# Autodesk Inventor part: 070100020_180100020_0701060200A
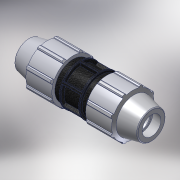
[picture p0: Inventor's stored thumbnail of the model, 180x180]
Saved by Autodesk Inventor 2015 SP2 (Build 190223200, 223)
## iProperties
Created: 2017-02
Part Number: 070100020_180100020_0701060200A
Material: PVC-Piping
Description: PLASSON COUPLER 20-20
Document SubType Name: Modeling
Designer: KIM
Mass: 92.6774 g
Surface Area: 199.44 cm^2
Volume: 66.1981 cm^3
Density: 1.4 g/cm^3
Appearance: PTFE
Author: KIM
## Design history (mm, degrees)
derived "07010.ipt"
feature "Solid1::07010.ipt"
tag "TaggingFeature1"
body "Solid1"
other parameters: "d1" = 122, "d4" = 10.16667, "d5" = 17.42857, "d7" = 48, "d8" = 36, "d9" = 17.42857, "d11" = 1.74286, "d12" = 38.4, "d13" = 120 deg, "d15" = 12 deg, "d16" = 43.2, "d18" = 1, "d19" = 35 deg, "d20" = 17.5 deg, "d21" = 44.64, "d23" = 0, "d25" = 360 deg, "d27" = 0.96, "d33" = 0.4, "d34" = 2.4, "d36" = 0, "d37" = 0.4, "d38" = 0.4, "d40" = 360 deg, "d42" = 26.84, "d43" = 1.44, "d46" = 0.6, "d49" = 59, "d50" = 16, "E_" = 48, "H_" = 122, "l_" = 59
